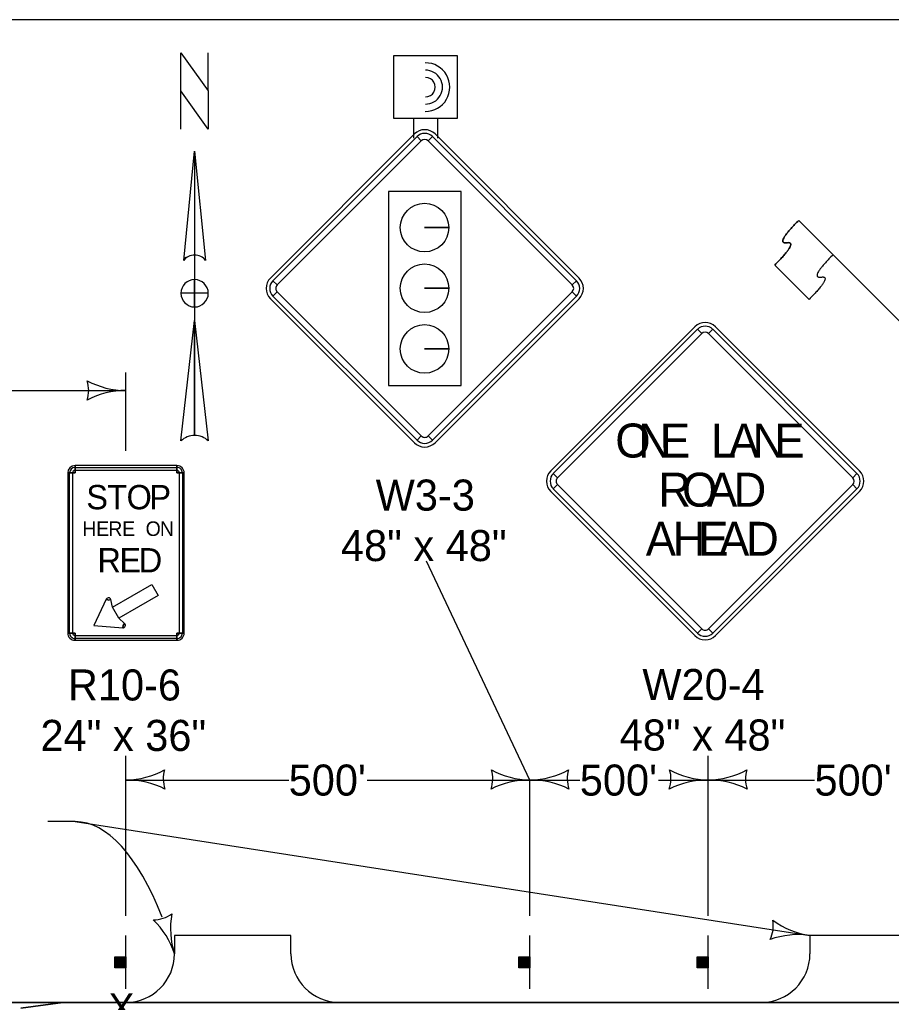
# Model space of a CAD drawing. Extents: x -2134934 to -2122394, y -2140205 to -2137036.
# Drawn here: x -2132569 to -2132120, y -2137542 to -2137036 of the extents above; entities that cross this region are included whole.
import ezdxf

# ---------------------------------------------------------------- set-up
doc = ezdxf.new("R2010")
doc.units = 0
for name, color, linetype in [('Barrier', 7, 'Continuous'), ('BridgeSuperStructureExisting', 7, 'Continuous'), ('Default', 7, 'Continuous'), ('dsnCellsScaleBlock', 7, 'Continuous'), ('DsnShtPlotIdentification', 7, 'Continuous'), ('DsnShtPlotShape', 7, 'Continuous'), ('TC_Barrier', 7, 'Continuous')]:
    doc.layers.add(name, color=color, linetype=linetype)

msp = doc.modelspace()

# ---------------------------------------------------------------- linework, layer by layer
at = {"layer": 'Barrier'}
for p, q in [((-2132365.82, -2137094.84), (-2132440.07, -2137169.09)), ((-2132364.5, -2137096.17), (-2132362.29, -2137098.38)), ((-2132358.75, -2137098.38), (-2132356.54, -2137096.17)), ((-2132280.97, -2137169.09), (-2132355.22, -2137094.84)), ((-2132110.46, -2137196.68), (-2132167.8, -2137139.38)), ((-2132167.8, -2137139.38), (-2132150.11, -2137157.06)), ((-2132348.11, -2137143.06), (-2132360.61, -2137143.06)), ((-2132360.61, -2137143.06), (-2132348.11, -2137143.06)), ((-2132162.49, -2137180.05), (-2132180.17, -2137162.37)), ((-2132436.53, -2137172.63), (-2132438.74, -2137170.42)), ((-2132282.3, -2137170.42), (-2132284.51, -2137172.63)), ((-2132438.74, -2137178.37), (-2132436.53, -2137176.16)), ((-2132348.11, -2137174.31), (-2132360.61, -2137174.31)), ((-2132360.61, -2137174.31), (-2132348.11, -2137174.31)), ((-2132284.51, -2137176.16), (-2132282.3, -2137178.37)), ((-2132440.07, -2137179.7), (-2132365.82, -2137253.94)), ((-2132355.22, -2137253.94), (-2132280.97, -2137179.7)), ((-2132221.34, -2137194.14), (-2132295.58, -2137268.39)), ((-2132220.01, -2137195.47), (-2132217.8, -2137197.68)), ((-2132214.27, -2137197.68), (-2132212.06, -2137195.47)), ((-2132136.48, -2137268.39), (-2132210.73, -2137194.14)), ((-2132348.11, -2137205.56), (-2132360.61, -2137205.56)), ((-2132360.61, -2137205.56), (-2132348.11, -2137205.56)), ((-2132362.29, -2137250.41), (-2132364.5, -2137252.62)), ((-2132356.54, -2137252.62), (-2132358.75, -2137250.41)), ((-2132544.45, -2137269.41), (-2132540.7, -2137269.41)), ((-2132543.51, -2137269.41), (-2132541.95, -2137269.41)), ((-2132540.7, -2137269.41), (-2132540.7, -2137265.66)), ((-2132540.7, -2137268.16), (-2132540.7, -2137266.6)), ((-2132488.2, -2137265.66), (-2132488.2, -2137269.41)), ((-2132488.2, -2137266.6), (-2132488.2, -2137268.16)), ((-2132488.2, -2137269.41), (-2132484.45, -2137269.41)), ((-2132486.95, -2137269.41), (-2132485.38, -2137269.41)), ((-2132292.05, -2137271.93), (-2132294.26, -2137269.72)), ((-2132137.81, -2137269.72), (-2132140.02, -2137271.93)), ((-2132295.58, -2137279), (-2132221.34, -2137353.24)), ((-2132294.26, -2137277.67), (-2132292.05, -2137275.46)), ((-2132210.73, -2137353.24), (-2132136.48, -2137279)), ((-2132140.02, -2137275.46), (-2132137.81, -2137277.67)), ((-2132524.59, -2137334.4), (-2132523.48, -2137334.98)), ((-2132523.48, -2137334.98), (-2132522.26, -2137334.7)), ((-2132515.98, -2137347.97), (-2132516.03, -2137349.22)), ((-2132515.13, -2137347.05), (-2132515.98, -2137347.97)), ((-2132217.8, -2137349.71), (-2132220.01, -2137351.92)), ((-2132212.06, -2137351.92), (-2132214.27, -2137349.71)), ((-2132540.7, -2137351.91), (-2132544.45, -2137351.91)), ((-2132541.95, -2137351.91), (-2132543.51, -2137351.91)), ((-2132540.7, -2137355.66), (-2132540.7, -2137351.91)), ((-2132540.7, -2137354.72), (-2132540.7, -2137353.16)), ((-2132484.45, -2137351.91), (-2132488.2, -2137351.91)), ((-2132488.2, -2137351.91), (-2132488.2, -2137355.66)), ((-2132488.2, -2137353.16), (-2132488.2, -2137354.72)), ((-2132485.38, -2137351.91), (-2132486.95, -2137351.91))]:
    msp.add_line(p, q, dxfattribs=at)
for points in [[(-2132364.5, -2137096.17), (-2132438.74, -2137170.42), (-2132436.53, -2137172.63), (-2132362.29, -2137098.38), (-2132364.5, -2137096.17)], [(-2132282.3, -2137170.42), (-2132356.54, -2137096.17), (-2132358.75, -2137098.38), (-2132284.51, -2137172.63), (-2132282.3, -2137170.42)], [(-2132341.79, -2137124.45), (-2132379.25, -2137124.45), (-2132379.25, -2137224.34), (-2132341.79, -2137224.34), (-2132341.79, -2137124.45)], [(-2132438.74, -2137178.37), (-2132364.5, -2137252.62), (-2132362.29, -2137250.41), (-2132436.53, -2137176.16), (-2132438.74, -2137178.37)], [(-2132356.54, -2137252.62), (-2132282.3, -2137178.37), (-2132284.51, -2137176.16), (-2132358.75, -2137250.41), (-2132356.54, -2137252.62)], [(-2132220.01, -2137195.47), (-2132294.26, -2137269.72), (-2132292.05, -2137271.93), (-2132217.8, -2137197.68), (-2132220.01, -2137195.47)], [(-2132137.81, -2137269.72), (-2132212.06, -2137195.47), (-2132214.27, -2137197.68), (-2132140.02, -2137271.93), (-2132137.81, -2137269.72)], [(-2132540.7, -2137355.66), (-2132488.2, -2137355.66), (-2132488.2, -2137351.91), (-2132484.45, -2137351.91), (-2132484.45, -2137269.41), (-2132488.2, -2137269.41), (-2132488.2, -2137265.66), (-2132540.7, -2137265.66), (-2132540.7, -2137269.41), (-2132544.45, -2137269.41), (-2132544.45, -2137351.91), (-2132540.7, -2137351.91), (-2132540.7, -2137355.66)], [(-2132541.95, -2137269.41), (-2132541.95, -2137351.91), (-2132543.51, -2137351.91), (-2132543.51, -2137269.41), (-2132541.95, -2137269.41)], [(-2132488.2, -2137268.16), (-2132540.7, -2137268.16), (-2132540.7, -2137266.6), (-2132488.2, -2137266.6), (-2132488.2, -2137268.16)], [(-2132486.95, -2137351.91), (-2132486.95, -2137269.41), (-2132485.38, -2137269.41), (-2132485.38, -2137351.91), (-2132486.95, -2137351.91)], [(-2132294.26, -2137277.67), (-2132220.01, -2137351.92), (-2132217.8, -2137349.71), (-2132292.05, -2137275.46), (-2132294.26, -2137277.67)], [(-2132212.06, -2137351.92), (-2132137.81, -2137277.67), (-2132140.02, -2137275.46), (-2132214.27, -2137349.71), (-2132212.06, -2137351.92)], [(-2132501.07, -2137326.91), (-2132497.79, -2137332.6), (-2132518.1, -2137344.32), (-2132521.38, -2137338.64), (-2132501.07, -2137326.91)], [(-2132531.1, -2137348.04), (-2132516.03, -2137349.22), (-2132515.98, -2137347.97), (-2132515.13, -2137347.05), (-2132518.1, -2137344.32), (-2132521.38, -2137338.64), (-2132522.26, -2137334.7), (-2132523.48, -2137334.98), (-2132524.59, -2137334.4), (-2132531.1, -2137348.04)], [(-2132540.7, -2137353.16), (-2132488.2, -2137353.16), (-2132488.2, -2137354.72), (-2132540.7, -2137354.72), (-2132540.7, -2137353.16)]]:
    msp.add_lwpolyline(points, close=True, dxfattribs=at)
for centre in [(-2132360.61, -2137143.06), (-2132360.61, -2137174.31), (-2132360.61, -2137205.56)]:
    msp.add_circle(centre, 12.5, dxfattribs=at)
for centre, radius, start, end in [((-2132360.52, -2137100.15), 7.5, 45, 134.9997), ((-2132360.52, -2137100.15), 5.62, 45, 134.9997), ((-2132360.52, -2137100.15), 2.5, 45, 134.9997), ((-2132434.77, -2137174.39), 7.5, 134.9997, 225), ((-2132434.77, -2137174.39), 5.62, 134.9997, 225), ((-2132434.77, -2137174.39), 2.5, 134.9997, 225), ((-2132286.28, -2137174.39), 2.5, 315.0002, 44.9998), ((-2132286.28, -2137174.39), 5.62, 315.0002, 44.9998), ((-2132286.28, -2137174.39), 7.5, 315.0002, 44.9998), ((-2132216.03, -2137199.45), 7.5, 45, 134.9997), ((-2132216.03, -2137199.45), 5.62, 45, 134.9997), ((-2132216.03, -2137199.45), 2.5, 45, 134.9997), ((-2132360.52, -2137248.64), 7.5, 225, 315.0002), ((-2132360.52, -2137248.64), 5.62, 225, 315.0002), ((-2132360.52, -2137248.64), 2.5, 225, 315.0002), ((-2132540.7, -2137269.41), 3.75, 90.0002, 179.9998), ((-2132540.7, -2137269.41), 2.81, 90.0002, 179.9998), ((-2132540.7, -2137269.41), 1.25, 90.0002, 179.9998), ((-2132488.2, -2137269.41), 3.75, 0, 90.0002), ((-2132488.2, -2137269.41), 2.81, 0, 90.0002), ((-2132488.2, -2137269.41), 1.25, 0, 90.0002), ((-2132290.28, -2137273.69), 7.5, 134.9997, 225), ((-2132141.79, -2137273.69), 7.5, 315.0002, 44.9998), ((-2132290.28, -2137273.69), 5.62, 134.9997, 225), ((-2132290.28, -2137273.69), 2.5, 134.9997, 225), ((-2132141.79, -2137273.69), 2.5, 315.0002, 44.9998), ((-2132141.79, -2137273.69), 5.62, 315.0002, 44.9998), ((-2132523.48, -2137334.98), 1.25, 12.6223, 152.2756), ((-2132515.98, -2137347.97), 1.25, 267.7243, 47.3776), ((-2132216.03, -2137347.94), 2.5, 225, 315.0002), ((-2132540.7, -2137351.91), 3.75, 179.9998, 270.0001), ((-2132540.7, -2137351.91), 2.81, 179.9998, 270.0001), ((-2132540.7, -2137351.91), 1.25, 179.9998, 270.0001), ((-2132488.2, -2137351.91), 3.75, 270.0001, 0.0003), ((-2132488.2, -2137351.91), 2.81, 270.0001, 0.0003), ((-2132488.2, -2137351.91), 1.25, 270.0001, 0.0003), ((-2132216.03, -2137347.94), 7.5, 225, 315.0002), ((-2132216.03, -2137347.94), 5.62, 225, 315.0002)]:
    msp.add_arc(centre, radius, start, end, dxfattribs=at)
for points in [[(-2132180.17, -2137162.37), (-2132167.8, -2137149.99), (-2132180.17, -2137151.77), (-2132167.8, -2137139.38)], [(-2132150.11, -2137157.06), (-2132162.49, -2137169.44), (-2132150.12, -2137167.67), (-2132162.49, -2137180.05)]]:
    msp.add_open_spline(points, degree=2, dxfattribs=at)
at = {"layer": 'BridgeSuperStructureExisting'}
for p, q in [((-2132366.36, -2137086.93), (-2132366.36, -2137096.93)), ((-2132353.86, -2137086.93), (-2132353.86, -2137096.93)), ((-2132514.45, -2137258.09), (-2132514.45, -2137217.69)), ((-2133178.02, -2137226.98), (-2132514.45, -2137226.98)), ((-2132306.28, -2137427.66), (-2132359.62, -2137314.86)), ((-2132514.45, -2137497.66), (-2132514.45, -2137415.16)), ((-2132214.45, -2137497.66), (-2132214.45, -2137415.16)), ((-2132514.45, -2137427.66), (-2132430.62, -2137427.66)), ((-2132390.12, -2137427.66), (-2132306.28, -2137427.66)), ((-2132306.28, -2137427.66), (-2132280.62, -2137427.66)), ((-2132306.28, -2137497.66), (-2132306.28, -2137427.66)), ((-2132240.12, -2137427.66), (-2132214.45, -2137427.66)), ((-2132214.45, -2137427.66), (-2132159.7, -2137427.66)), ((-2132540.56, -2137449.08), (-2132554.78, -2137449.08)), ((-2132540.56, -2137449.08), (-2132162.05, -2137507.67)), ((-2132514.45, -2137535.16), (-2132514.45, -2137507.66)), ((-2132306.28, -2137535.16), (-2132306.28, -2137507.66)), ((-2132214.45, -2137535.16), (-2132214.45, -2137507.66)), ((-2132519.77, -2137524.3), (-2132519.77, -2137518.71)), ((-2132519.45, -2137518.71), (-2132519.45, -2137524.3)), ((-2132519.23, -2137524.3), (-2132519.23, -2137518.71)), ((-2132518.91, -2137518.71), (-2132518.91, -2137524.3)), ((-2132518.68, -2137524.3), (-2132518.7, -2137518.71)), ((-2132518.27, -2137518.71), (-2132518.25, -2137524.3)), ((-2132518.05, -2137524.3), (-2132518.05, -2137518.71)), ((-2132517.62, -2137518.71), (-2132517.62, -2137524.3)), ((-2132517.24, -2137524.3), (-2132517.24, -2137518.71)), ((-2132516.92, -2137518.71), (-2132516.9, -2137524.3)), ((-2132516.7, -2137524.3), (-2132516.7, -2137518.71)), ((-2132516.43, -2137518.71), (-2132516.43, -2137524.3)), ((-2132516.1, -2137524.3), (-2132516.1, -2137518.71)), ((-2132515.89, -2137518.71), (-2132515.89, -2137524.3)), ((-2132515.67, -2137524.3), (-2132515.67, -2137518.71)), ((-2132515.4, -2137518.71), (-2132515.4, -2137524.3)), ((-2132515.14, -2137524.3), (-2132515.14, -2137518.71)), ((-2132514.86, -2137518.71), (-2132514.86, -2137524.3)), ((-2132311.61, -2137524.3), (-2132311.61, -2137518.71)), ((-2132311.29, -2137518.71), (-2132311.29, -2137524.3)), ((-2132311.07, -2137524.3), (-2132311.07, -2137518.71)), ((-2132310.75, -2137518.71), (-2132310.75, -2137524.3)), ((-2132310.52, -2137524.3), (-2132310.54, -2137518.71)), ((-2132310.11, -2137518.71), (-2132310.09, -2137524.3)), ((-2132309.89, -2137524.3), (-2132309.89, -2137518.71)), ((-2132309.45, -2137518.71), (-2132309.45, -2137524.3)), ((-2132309.08, -2137524.3), (-2132309.08, -2137518.71)), ((-2132308.76, -2137518.71), (-2132308.74, -2137524.3)), ((-2132308.54, -2137524.3), (-2132308.54, -2137518.71)), ((-2132308.27, -2137518.71), (-2132308.27, -2137524.3)), ((-2132307.94, -2137524.3), (-2132307.94, -2137518.71)), ((-2132307.73, -2137518.71), (-2132307.73, -2137524.3)), ((-2132307.5, -2137524.3), (-2132307.5, -2137518.71)), ((-2132307.24, -2137518.71), (-2132307.24, -2137524.3)), ((-2132306.98, -2137524.3), (-2132306.98, -2137518.71)), ((-2132306.7, -2137518.71), (-2132306.7, -2137524.3)), ((-2132219.77, -2137524.3), (-2132219.77, -2137518.71)), ((-2132219.45, -2137518.71), (-2132219.45, -2137524.3)), ((-2132219.23, -2137524.3), (-2132219.23, -2137518.71)), ((-2132218.91, -2137518.71), (-2132218.91, -2137524.3)), ((-2132218.69, -2137524.3), (-2132218.7, -2137518.71)), ((-2132218.27, -2137518.71), (-2132218.25, -2137524.3)), ((-2132218.05, -2137524.3), (-2132218.05, -2137518.71)), ((-2132217.62, -2137518.71), (-2132217.62, -2137524.3)), ((-2132217.24, -2137524.3), (-2132217.24, -2137518.71)), ((-2132216.92, -2137518.71), (-2132216.9, -2137524.3)), ((-2132216.7, -2137524.3), (-2132216.7, -2137518.71)), ((-2132216.43, -2137518.71), (-2132216.43, -2137524.3)), ((-2132216.1, -2137524.3), (-2132216.1, -2137518.71)), ((-2132215.89, -2137518.71), (-2132215.89, -2137524.3)), ((-2132215.67, -2137524.3), (-2132215.67, -2137518.71)), ((-2132215.4, -2137518.71), (-2132215.4, -2137524.3)), ((-2132215.14, -2137524.3), (-2132215.14, -2137518.71)), ((-2132214.86, -2137518.71), (-2132214.86, -2137524.3)), ((-2132514.45, -2137542.16), (-2132404.45, -2137542.16)), ((-2132187.05, -2137542.16), (-2132077.05, -2137542.16))]:
    msp.add_line(p, q, dxfattribs=at)
for points in [[(-2132376.36, -2137086.93), (-2132376.36, -2137054.43), (-2132343.86, -2137054.43), (-2132343.86, -2137086.93)], [(-2132514.54, -2137518.71), (-2132514.54, -2137524.34), (-2132520.17, -2137524.34), (-2132520.17, -2137518.71)], [(-2132306.38, -2137518.71), (-2132306.38, -2137524.34), (-2132312, -2137524.34), (-2132312, -2137518.71)], [(-2132214.54, -2137518.71), (-2132214.54, -2137524.34), (-2132220.17, -2137524.34), (-2132220.17, -2137518.71)]]:
    msp.add_lwpolyline(points, close=True, dxfattribs=at)
for points in [[(-2132429.45, -2137517.16), (-2132429.45, -2137507.67), (-2132489.45, -2137507.67), (-2132489.45, -2137517.16)], [(-2132102.05, -2137517.16), (-2132102.05, -2137507.67), (-2132162.05, -2137507.67), (-2132162.05, -2137517.16)]]:
    msp.add_lwpolyline(points, dxfattribs=at)
for centre, radius, start, end in [((-2132360.1, -2137070.7), 12.5, 269.4041, 90.5445), ((-2132360.1, -2137070.7), 12.5, 269.4041, 90.5445), ((-2132360.1, -2137070.7), 8.75, 269.4041, 90.5445), ((-2132360.1, -2137070.7), 5, 269.4041, 90.5445), ((-2132515.2, -2137385.17), 42.5, 271.0176, 299.0725), ((-2132478.83, -2137427.04), 16.42, 163.2666, 198.7334), ((-2132341.9, -2137427.04), 16.42, 341.2666, 16.7334), ((-2132305.53, -2137385.17), 42.5, 240.9275, 268.9824), ((-2132307.04, -2137385.17), 42.5, 271.0176, 299.0725), ((-2132270.67, -2137427.04), 16.42, 163.2666, 198.7334), ((-2132250.06, -2137427.04), 16.42, 341.2666, 16.7334), ((-2132213.69, -2137385.17), 42.5, 240.9275, 268.9824), ((-2132215.2, -2137385.17), 42.5, 271.0176, 299.0725), ((-2132178.83, -2137427.04), 16.42, 163.2666, 198.7334), ((-2132513.72, -2137470.15), 42.5, 62.9275, 90.9824), ((-2132307.01, -2137470.15), 42.5, 89.0176, 117.0725), ((-2132305.56, -2137470.15), 42.5, 62.9275, 90.9824), ((-2132215.17, -2137470.15), 42.5, 89.0176, 117.0725), ((-2132213.72, -2137470.15), 42.5, 62.9275, 90.9824), ((-2132514.45, -2137517.16), 25, 270, 0), ((-2132404.45, -2137517.16), 25, 180, 270), ((-2132187.05, -2137517.16), 25, 270, 0)]:
    msp.add_arc(centre, radius, start, end, dxfattribs=at)
msp.add_ellipse((-2132540.56, -2137662.01), major_axis=(0, 212.93), ratio=0.328743, start_param=5.590023, end_param=6.283185, dxfattribs=at)
at = {"layer": 'Default'}
msp.add_lwpolyline([(-2134934.44, -2137035.95), (-2131799.45, -2137035.95), (-2131799.45, -2139045.94), (-2134934.44, -2139045.94)], close=True, dxfattribs=at)
at = {"layer": 'dsnCellsScaleBlock'}
for p, q in [((-2132479.07, -2137103.67), (-2132473.43, -2137160.01)), ((-2132479.07, -2137103.67), (-2132479.07, -2137250.16)), ((-2132484.7, -2137160.01), (-2132484.7, -2137160.01)), ((-2132484.48, -2137159.49), (-2132483.43, -2137158.32)), ((-2132479.07, -2137183.96), (-2132479.07, -2137183.96)), ((-2132486.11, -2137252.98), (-2132479.07, -2137191))]:
    msp.add_line(p, q, dxfattribs=at)
msp.add_lwpolyline([(-2132472.02, -2137092.4), (-2132486.11, -2137072.68), (-2132486.11, -2137052.97), (-2132472.02, -2137072.68)], close=True, dxfattribs=at)
for points in [[(-2132486.11, -2137092.4), (-2132486.11, -2137052.97), (-2132472.02, -2137072.68), (-2132472.02, -2137052.97)], [(-2132484.7, -2137160.01), (-2132479.07, -2137103.67), (-2132479.07, -2137157.2)], [(-2132472.02, -2137176.92), (-2132479.07, -2137176.92), (-2132479.07, -2137169.87)], [(-2132479.07, -2137183.96), (-2132479.07, -2137176.92), (-2132486.11, -2137176.92)], [(-2132479.07, -2137250.16), (-2132479.07, -2137191), (-2132472.02, -2137252.98)]]:
    msp.add_lwpolyline(points, dxfattribs=at)
for centre, radius, start, end in [((-2132479.07, -2137164.24), 7.04, 90.0204, 143.1257), ((-2132479.07, -2137164.23), 7.04, 36.8481, 90.0218), ((-2132479.07, -2137176.92), 7.04, 90, 180), ((-2132479.07, -2137176.92), 7.04, 360, 90), ((-2132479.07, -2137176.92), 7.04, 180, 270), ((-2132479.07, -2137176.92), 7.04, 270, 360), ((-2132479.07, -2137260.36), 10.2, 89.9894, 133.619), ((-2132479.07, -2137260.37), 10.21, 46.4021, 90.0006)]:
    msp.add_arc(centre, radius, start, end, dxfattribs=at)
at = {"layer": 'DsnShtPlotIdentification'}
for p, q in [((-2132547.01, -2137542.16), (-2132860.67, -2137542.16)), ((-2132547.01, -2137542.16), (-2132568.69, -2137545.16)), ((-2132568.69, -2137545.16), (-2132547.01, -2137542.16)), ((-2131861.99, -2137542.16), (-2132547.01, -2137542.16))]:
    msp.add_line(p, q, dxfattribs=at)
msp.add_lwpolyline([(-2133174.44, -2137542.16), (-2131861.99, -2137542.16)], dxfattribs=at)
at = {"layer": 'DsnShtPlotShape'}
for centre, radius, start, end in [((-2132550.08, -2137226.98), 16.42, 342.2666, 17.7333), ((-2132514.45, -2137184.48), 42.5, 241.9275, 270), ((-2132514.45, -2137269.48), 42.5, 90, 118.0725), ((-2132500.41, -2137483.25), 16.42, 270.1817, 305.6484), ((-2132449.01, -2137504.09), 42.5, 169.8426, 197.9151), ((-2132529.89, -2137530.23), 42.5, 17.9151, 45.9876), ((-2132197.33, -2137502.65), 16.42, 334.1738, 9.6405), ((-2132156.07, -2137465.59), 42.5, 233.8346, 261.9071), ((-2132168.03, -2137549.75), 42.5, 81.9071, 109.9796)]:
    msp.add_arc(centre, radius, start, end, dxfattribs=at)
at = {"layer": 'TC_Barrier'}
msp.add_line((-2132180.17, -2137162.37), (-2132162.49, -2137180.05), dxfattribs=at)
for points in [[(-2132167.8, -2137139.38), (-2132180.17, -2137151.77), (-2132167.8, -2137149.99), (-2132180.17, -2137162.37)], [(-2132150.11, -2137157.06), (-2132162.49, -2137169.44), (-2132150.12, -2137167.67), (-2132162.49, -2137180.05)]]:
    msp.add_open_spline(points, degree=2, dxfattribs=at)

# ---------------------------------------------------------------- texts
at = {"layer": 'Barrier'}
for s, height, p in [('O', 17.5, (-2132262.32, -2137261.51)), ('N', 17.5, (-2132250.54, -2137261.51)), ('E', 17.5, (-2132239.32, -2137261.51)), ('L', 17.5, (-2132213.07, -2137261.51)), ('A', 17.5, (-2132203.87, -2137261.51)), ('N', 17.5, (-2132191.6, -2137261.51)), ('E', 17.5, (-2132180.37, -2137261.51)), ('R', 17.5, (-2132240.21, -2137286.82)), ('O', 17.5, (-2132227.92, -2137286.82)), ('A', 17.5, (-2132215.08, -2137286.82)), ('D', 17.5, (-2132201.43, -2137286.82)), ('W3-3', 16, (-2132385.81, -2137288.86)), ('S', 12.5, (-2132534.89, -2137288.16)), ('T', 12.5, (-2132524.13, -2137288.16)), ('O', 12.5, (-2132514.14, -2137288.16)), ('P', 12.5, (-2132502.4, -2137288.16)), ('H', 7.5, (-2132536.97, -2137301.91)), ('E', 7.5, (-2132529.82, -2137301.91)), ('R', 7.5, (-2132523.56, -2137301.91)), ('E', 7.5, (-2132516.41, -2137301.91)), ('O', 7.5, (-2132504.34, -2137301.91)), ('N', 7.5, (-2132496.96, -2137301.91)), ('A', 17.5, (-2132246.65, -2137312.13)), ('H', 17.5, (-2132232.78, -2137312.13)), ('E', 17.5, (-2132219.57, -2137312.13)), ('A', 17.5, (-2132208.85, -2137312.13)), ('D', 17.5, (-2132194.99, -2137312.13)), ('48" x 48"', 16, (-2132403.69, -2137314.86)), ('R', 12.5, (-2132529.13, -2137320.66)), ('E', 12.5, (-2132517.8, -2137320.66)), ('D', 12.5, (-2132507.84, -2137320.66)), ('R10-6', 16, (-2132544.37, -2137386.66)), ('W20-4', 16, (-2132248.4, -2137386.44)), ('24" x 36"', 16, (-2132558.51, -2137412.66)), ('48" x 48"', 16, (-2132260.1, -2137412.44))]:
    msp.add_text(s, height=height, dxfattribs=at).set_placement(p)
at = {"layer": 'BridgeSuperStructureExisting'}
for s, height, p in [("500'", 16, (-2132430.62, -2137435.66)), ("500'", 16, (-2132280.62, -2137435.66)), ("500'", 16, (-2132159.7, -2137435.66)), ('X', 15, (-2132523.45, -2137552.51))]:
    msp.add_text(s, height=height, dxfattribs=at).set_placement(p)

doc.saveas('drawing.dxf')
